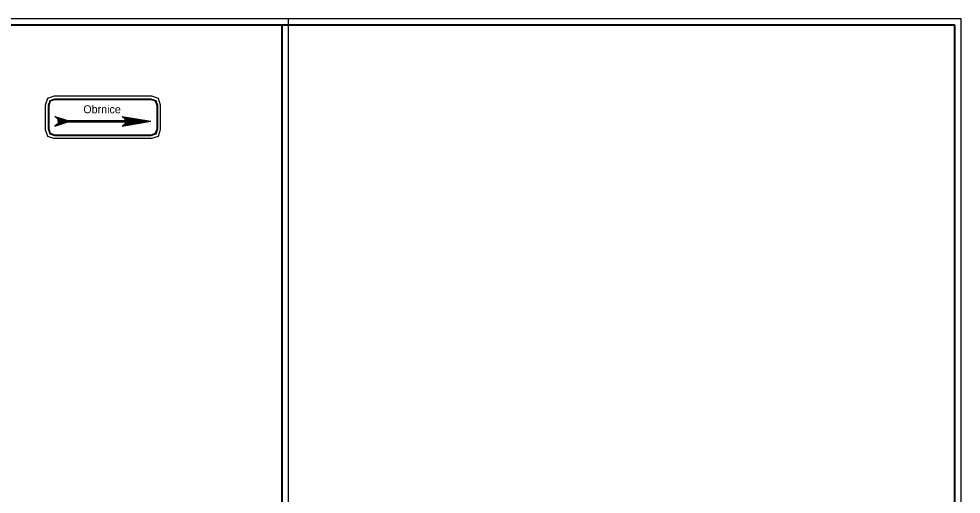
# Model space of a CAD drawing. Extents: x 0 to 10087, y -805 to 297.
# Drawn here: x 8342.1 to 8636.3, y 148.5 to 297 of the extents above; entities that cross this region are included whole.
import ezdxf

# ---------------------------------------------------------------- set-up
doc = ezdxf.new("R2010")
doc.units = 0
for name, color, linetype in [('RAM', 7, 'Continuous'), ('SMER_SIPKY_TEXT', 7, 'Continuous'), ('SMER_SIPKY_TVAR', 7, 'Continuous')]:
    doc.layers.add(name, color=color, linetype=linetype)

msp = doc.modelspace()

# ---------------------------------------------------------------- linework, layer by layer
at = {"layer": 'RAM'}
for p, q in [((8636.33, 297), (0, 297)), ((8634.33, 295.1), (2, 295.1)), ((8634.33, 295), (2, 295)), ((8634.33, 294.9), (2, 294.9)), ((8424.23, 2), (8424.23, 295)), ((8424.33, 2), (8424.33, 295)), ((8424.43, 2), (8424.43, 295)), ((8426.33, 0), (8426.33, 297)), ((8426.33, 293), (8426.33, 297)), ((8634.23, 2), (8634.23, 295)), ((8634.33, 2), (8634.33, 295)), ((8634.43, 2), (8634.43, 295)), ((8636.33, 293), (8636.33, 297)), ((8636.33, 0), (8636.33, 297))]:
    msp.add_line(p, q, dxfattribs=at)
at = {"layer": 'SMER_SIPKY_TVAR'}
for p, q in [((8350.43, 270.15), (8351.12, 272.21)), ((8351.12, 272.21), (8353.19, 272.9)), ((8351.33, 270), (8351.83, 271.5)), ((8351.43, 269.98), (8351.91, 271.42)), ((8351.53, 269.97), (8351.99, 271.34)), ((8351.83, 271.5), (8353.33, 272)), ((8351.91, 271.42), (8353.35, 271.9)), ((8351.99, 271.34), (8353.36, 271.8)), ((8353.19, 272.9), (8383.48, 272.9)), ((8353.33, 272), (8383.33, 272)), ((8353.35, 271.9), (8383.32, 271.9)), ((8353.36, 271.8), (8383.3, 271.8)), ((8383.3, 271.8), (8384.67, 271.34)), ((8383.32, 271.9), (8384.75, 271.42)), ((8383.33, 272), (8384.83, 271.5)), ((8383.48, 272.9), (8385.54, 272.21)), ((8384.67, 271.34), (8385.13, 269.97)), ((8384.75, 271.42), (8385.23, 269.98)), ((8384.83, 271.5), (8385.33, 270)), ((8385.54, 272.21), (8386.23, 270.15)), ((8350.43, 262.35), (8350.43, 270.15)), ((8351.33, 262.5), (8351.33, 270)), ((8351.43, 262.52), (8351.43, 269.98)), ((8351.53, 262.53), (8351.53, 269.97)), ((8385.13, 269.97), (8385.13, 262.53)), ((8385.23, 269.98), (8385.23, 262.52)), ((8385.33, 270), (8385.33, 262.5)), ((8386.23, 270.15), (8386.23, 262.35)), ((8354.33, 265.7), (8353.33, 266.5)), ((8353.33, 266.5), (8357.33, 265.2)), ((8353.53, 266.3), (8353.93, 266.3)), ((8353.83, 266.1), (8354.43, 266.1)), ((8354.03, 265.9), (8355.08, 265.9)), ((8354.33, 265.7), (8355.73, 265.7)), ((8354.33, 265), (8354.33, 265.7)), ((8354.33, 265.5), (8356.33, 265.5)), ((8354.33, 265.3), (8357.03, 265.3)), ((8354.33, 265.1), (8382.53, 265.1)), ((8354.33, 265), (8354.33, 264.3)), ((8354.33, 264.9), (8382.53, 264.9)), ((8357.33, 265.2), (8375.33, 265.2)), ((8375.33, 265.7), (8374.33, 266.5)), ((8374.33, 266.5), (8383.33, 265)), ((8374.33, 263.5), (8383.33, 265)), ((8374.53, 266.3), (8375.53, 266.3)), ((8374.83, 266.1), (8376.83, 266.1)), ((8375.13, 265.9), (8377.23, 265.9)), ((8375.33, 265.7), (8378.53, 265.7)), ((8375.33, 265.2), (8375.33, 265.7)), ((8375.33, 265.5), (8379.83, 265.5)), ((8375.33, 265.3), (8381.23, 265.3)), ((8351.12, 260.29), (8350.43, 262.35)), ((8351.83, 261), (8351.33, 262.5)), ((8351.91, 261.08), (8351.43, 262.52)), ((8351.99, 261.16), (8351.53, 262.53)), ((8353.33, 263.5), (8357.33, 264.8)), ((8354.33, 264.3), (8353.33, 263.5)), ((8353.53, 263.7), (8353.93, 263.7)), ((8353.83, 263.9), (8354.43, 263.9)), ((8354.03, 264.1), (8355.08, 264.1)), ((8354.33, 264.7), (8357.03, 264.7)), ((8354.33, 264.5), (8356.33, 264.5)), ((8354.33, 264.3), (8355.73, 264.3)), ((8357.33, 264.8), (8375.33, 264.8)), ((8375.33, 264.3), (8374.33, 263.5)), ((8374.53, 263.7), (8375.53, 263.7)), ((8374.83, 263.9), (8376.83, 263.9)), ((8375.13, 264.1), (8377.23, 264.1)), ((8375.33, 264.8), (8375.33, 264.3)), ((8375.33, 264.7), (8381.23, 264.7)), ((8375.33, 264.5), (8379.83, 264.5)), ((8375.33, 264.3), (8378.53, 264.3)), ((8385.13, 262.53), (8384.67, 261.16)), ((8385.23, 262.52), (8384.75, 261.08)), ((8385.33, 262.5), (8384.83, 261)), ((8386.23, 262.35), (8385.54, 260.29)), ((8353.05, 259.65), (8351.12, 260.29)), ((8353.33, 260.5), (8351.83, 261)), ((8353.36, 260.59), (8351.91, 261.08)), ((8353.39, 260.69), (8351.99, 261.16)), ((8383.48, 259.6), (8353.05, 259.65)), ((8383.33, 260.5), (8353.33, 260.5)), ((8383.32, 260.6), (8353.36, 260.59)), ((8383.3, 260.7), (8353.39, 260.69)), ((8384.67, 261.16), (8383.3, 260.7)), ((8384.75, 261.08), (8383.32, 260.6)), ((8384.83, 261), (8383.33, 260.5)), ((8385.54, 260.29), (8383.48, 259.6))]:
    msp.add_line(p, q, dxfattribs=at)

# ---------------------------------------------------------------- texts
at = {"layer": 'SMER_SIPKY_TEXT'}
msp.add_text('Obrnice', height=2.5, dxfattribs=at).set_placement((8362.21, 267.5))

doc.saveas('drawing.dxf')
